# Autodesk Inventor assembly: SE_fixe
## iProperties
Shininess: 64.0
Length Units: 11269
Angle Units: 11279
Time Units: 11290
Mass Units: 11283
Length Display Precision: 3
Angle Display Precision: 2
Compacted: True
Created: 2003-11
Part Number: SE_fixe
Document SubType Name: Assembly
Designer: Flavien MARTY
Density: 0.0
Volumn: 0.0
Area: 0.0
PropertySet Name: Model Information
Control State: 0
Master: False
Checked Out: False
Author: Flavien MARTY
